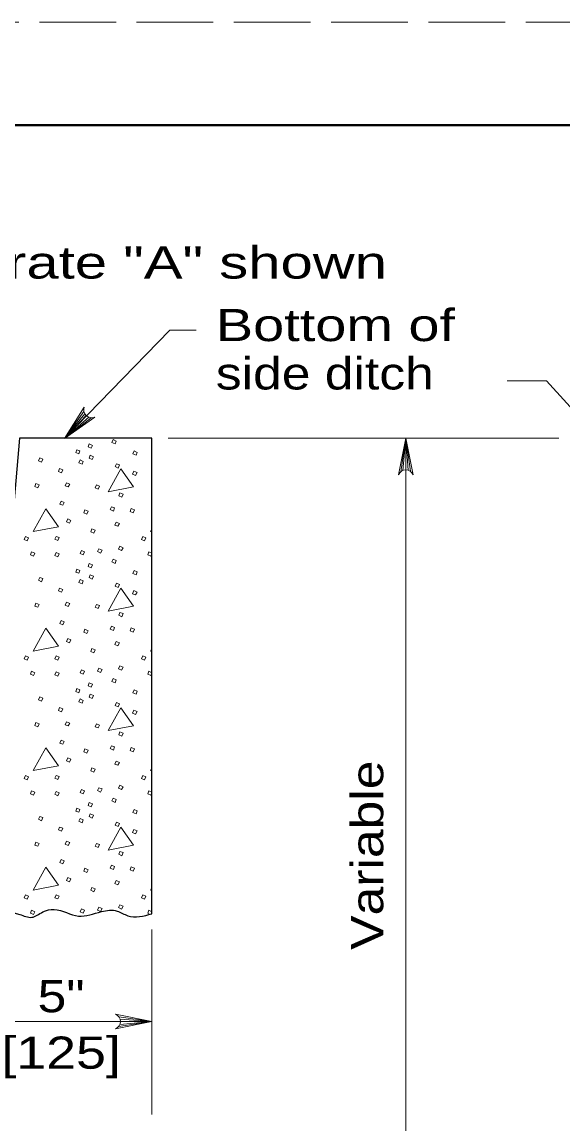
# Model space of a CAD drawing. Extents: x 1036.7 to 1070.7, y 883.9 to 905.9.
# Drawn here: x 1055.59 to 1058.21, y 900.56 to 905.91 of the extents above; entities that cross this region are included whole.
import ezdxf
from ezdxf.enums import TextEntityAlignment as Align

# ---------------------------------------------------------------- set-up
doc = ezdxf.new("R2010")
doc.units = 0
doc.header["$LTSCALE"] = 0.062
doc.linetypes.add('LONG_DASHED', pattern=[7.5, 6, -1.5])
doc.layers.add('1', color=7, linetype='Continuous', lineweight=13)

msp = doc.modelspace()

# ---------------------------------------------------------------- linework, layer by layer
at = {"layer": '1', "lineweight": 25}
for p, q in [((1038.67333, 905.40825), (1070.17333, 905.40825)), ((1056.21542, 901.58258), (1056.21542, 903.88892))]:
    msp.add_line(p, q, dxfattribs=at)
at = {"layer": '1'}
for p, q in [((1055.79083, 903.88783), (1056.30283, 904.41408)), ((1056.4305, 904.41408), (1056.30283, 904.41408)), ((1057.94, 904.16733), (1058.131, 904.16733)), ((1058.37525, 903.8975), (1058.131, 904.16733)), ((1055.88492, 904.0195), (1055.79083, 903.88783)), ((1055.88917, 904.00792), (1055.79083, 903.88783)), ((1055.89625, 903.99892), (1055.79083, 903.88783)), ((1055.90867, 903.99108), (1055.79083, 903.88783)), ((1055.92042, 903.98842), (1055.79083, 903.88783)), ((1056.29358, 903.88892), (1058.18042, 903.88892)), ((1058.19033, 903.88892), (1056.29992, 903.88892)), ((1057.42275, 903.72675), (1057.4475, 903.88892)), ((1057.43308, 903.73292), (1057.4475, 903.88892)), ((1057.4475, 900.62258), (1057.4475, 903.88892)), ((1057.4475, 903.73575), (1057.4475, 903.88892)), ((1057.45883, 903.73408), (1057.4475, 903.88892)), ((1057.46992, 903.72867), (1057.4475, 903.88892)), ((1056.20117, 903.338), (1056.21542, 903.33133)), ((1056.20117, 902.75833), (1056.21542, 902.75167)), ((1056.20117, 902.17867), (1056.21542, 902.172)), ((1056.20117, 901.599), (1056.21542, 901.59233)), ((1056.21542, 901.59025), (1056.212, 901.58233)), ((1056.21542, 901.50508), (1056.21542, 900.60858)), ((1055.32617, 901.05958), (1056.21542, 901.05958)), ((1056.05333, 901.03475), (1056.21542, 901.05958)), ((1056.05517, 901.082), (1056.21542, 901.05958)), ((1056.05942, 901.04517), (1056.21542, 901.05958)), ((1056.06058, 901.07092), (1056.21542, 901.05958)), ((1056.06225, 901.05958), (1056.21542, 901.05958)), ((1057.4475, 900.62258), (1057.4475, 899.32858))]:
    msp.add_line(p, q, dxfattribs=at)
at = {"layer": '1', "linetype": 'LONG_DASHED'}
msp.add_lwpolyline([(1036.67333, 883.90825), (1070.67333, 883.90825), (1070.67333, 905.90825), (1036.67333, 905.90825)], close=True, dxfattribs=at)
at = {"layer": '1', "lineweight": 40}
msp.add_lwpolyline([(1038.67333, 905.40825), (1070.17333, 905.40825), (1070.17333, 884.40825), (1038.67333, 884.40825)], close=True, dxfattribs=at)
msp.add_lwpolyline([(1038.67333, 905.40825), (1070.17333, 905.40825), (1070.17333, 884.40825), (1038.67333, 884.40825)], close=True, dxfattribs=at)
at = {"layer": '1'}
for points in [[(1055.93833, 903.99183), (1055.79083, 903.88783), (1055.887, 904.04058)], [(1057.41208, 903.71192), (1057.4475, 903.88892), (1057.48292, 903.71192)], [(1056.21542, 903.44892), (1056.20817, 903.43592), (1056.21542, 903.43733)], [(1056.21542, 903.32925), (1056.21017, 903.317), (1056.19517, 903.324), (1056.20117, 903.338)], [(1056.21542, 902.86925), (1056.20817, 902.85625), (1056.21542, 902.85767)], [(1056.21542, 902.74958), (1056.21017, 902.73733), (1056.19517, 902.74433), (1056.20117, 902.75833)], [(1056.21542, 902.28958), (1056.20817, 902.27658), (1056.21542, 902.278)], [(1056.21542, 902.16992), (1056.21017, 902.15767), (1056.19517, 902.16467), (1056.20117, 902.17867)], [(1056.21542, 901.70992), (1056.20817, 901.69692), (1056.21542, 901.69833)], [(1056.20267, 901.5815), (1056.19517, 901.585), (1056.20117, 901.599)], [(1056.03842, 901.02417), (1056.21542, 901.05958), (1056.03842, 901.095)]]:
    msp.add_lwpolyline(points, dxfattribs=at)
at = {"layer": '1', "lineweight": 25}
msp.add_lwpolyline([(1056.21542, 903.88892), (1055.57342, 903.88892), (1055.53433, 903.43767)], dxfattribs=at)
at = {"layer": '1'}
for points in [[(1056.02725, 903.88267), (1056.04225, 903.87567), (1056.03625, 903.86167), (1056.02125, 903.86867)], [(1055.85133, 903.83367), (1055.86633, 903.82767), (1055.86033, 903.81367), (1055.84533, 903.81967)], [(1055.91133, 903.86167), (1055.92633, 903.85467), (1055.92033, 903.84067), (1055.90533, 903.84667)], [(1056.12925, 903.82767), (1056.14417, 903.82067), (1056.13825, 903.80667), (1056.12325, 903.81267)], [(1055.67142, 903.79367), (1055.68642, 903.78767), (1055.67942, 903.77267), (1055.66442, 903.77967)], [(1055.86733, 903.78367), (1055.88233, 903.77667), (1055.87633, 903.76275), (1055.86133, 903.76975)], [(1055.91633, 903.80667), (1055.93133, 903.79967), (1055.92533, 903.78567), (1055.91033, 903.79267)], [(1056.04325, 903.76575), (1056.05825, 903.75975), (1056.05225, 903.74475), (1056.03725, 903.75175)], [(1055.76742, 903.74175), (1055.78242, 903.73575), (1055.77642, 903.72175), (1055.76142, 903.72775)], [(1056.06425, 903.74075), (1056.00225, 903.62975), (1056.12525, 903.65375)], [(1056.12825, 903.72975), (1056.14317, 903.72275), (1056.13625, 903.70875), (1056.12125, 903.71475)], [(1055.65242, 903.66875), (1055.66742, 903.66275), (1055.66142, 903.64875), (1055.64642, 903.65475)], [(1055.80133, 903.67275), (1055.81633, 903.66675), (1055.80933, 903.65275), (1055.79433, 903.65875)], [(1055.94633, 903.66275), (1055.96133, 903.65675), (1055.95433, 903.64275), (1055.93933, 903.64875)], [(1056.06025, 903.62383), (1056.07525, 903.61783), (1056.06925, 903.60283), (1056.05425, 903.60983)], [(1055.70042, 903.54683), (1055.63842, 903.43592), (1055.76142, 903.45992)], [(1055.77442, 903.58383), (1055.78933, 903.57783), (1055.78342, 903.56383), (1055.76842, 903.56983)], [(1056.01925, 903.55683), (1056.03425, 903.55083), (1056.02825, 903.53583), (1056.01325, 903.54283)], [(1056.11525, 903.54883), (1056.13025, 903.54183), (1056.12425, 903.52783), (1056.10925, 903.53383)], [(1055.80733, 903.49783), (1055.82233, 903.49083), (1055.81533, 903.47692), (1055.80033, 903.48292)], [(1055.89033, 903.54183), (1055.90533, 903.53483), (1055.89933, 903.52083), (1055.88433, 903.52783)], [(1055.92433, 903.44892), (1055.93933, 903.44292), (1055.93333, 903.42792), (1055.91833, 903.43492)], [(1056.04225, 903.48192), (1056.05725, 903.47592), (1056.05025, 903.46192), (1056.03525, 903.46792)], [(1055.6015, 903.41292), (1055.61642, 903.40592), (1055.61042, 903.39192), (1055.5955, 903.39792)], [(1055.75042, 903.41292), (1055.76542, 903.40692), (1055.75842, 903.39292), (1055.74342, 903.39892)], [(1056.17117, 903.41292), (1056.18617, 903.40592), (1056.18017, 903.39192), (1056.16517, 903.39792)], [(1055.63142, 903.338), (1055.64642, 903.331), (1055.64042, 903.317), (1055.62542, 903.324)], [(1055.75042, 903.335), (1055.76542, 903.329), (1055.75842, 903.314), (1055.74342, 903.321)], [(1055.87333, 903.34492), (1055.88833, 903.338), (1055.88233, 903.324), (1055.86733, 903.33)], [(1055.95833, 903.35292), (1055.97325, 903.34692), (1055.96625, 903.332), (1055.95133, 903.339)], [(1056.06025, 903.36492), (1056.07525, 903.35792), (1056.06825, 903.34392), (1056.05325, 903.35092)], [(1055.91133, 903.282), (1055.92633, 903.275), (1055.92033, 903.261), (1055.90533, 903.267)], [(1056.02725, 903.303), (1056.04225, 903.296), (1056.03625, 903.282), (1056.02125, 903.289)], [(1055.85133, 903.254), (1055.86633, 903.248), (1055.86033, 903.234), (1055.84533, 903.24)], [(1055.91633, 903.227), (1055.93133, 903.22), (1055.92533, 903.206), (1055.91033, 903.213)], [(1056.12925, 903.248), (1056.14417, 903.241), (1056.13825, 903.227), (1056.12325, 903.233)], [(1055.67142, 903.214), (1055.68642, 903.208), (1055.67942, 903.193), (1055.66442, 903.2)], [(1055.86733, 903.204), (1055.88233, 903.197), (1055.87633, 903.18308), (1055.86133, 903.19008)], [(1056.04325, 903.18608), (1056.05825, 903.18008), (1056.05225, 903.16508), (1056.03725, 903.17208)], [(1055.76742, 903.16208), (1055.78242, 903.15608), (1055.77642, 903.14208), (1055.76142, 903.14808)], [(1056.06425, 903.16108), (1056.00225, 903.05008), (1056.12525, 903.07408)], [(1056.12825, 903.15008), (1056.14317, 903.14308), (1056.13625, 903.12908), (1056.12125, 903.13508)], [(1055.65242, 903.08908), (1055.66742, 903.08308), (1055.66142, 903.06908), (1055.64642, 903.07508)], [(1055.80133, 903.09308), (1055.81633, 903.08708), (1055.80933, 903.07308), (1055.79433, 903.07908)], [(1055.94633, 903.08308), (1055.96133, 903.07708), (1055.95433, 903.06308), (1055.93933, 903.06908)], [(1056.06025, 903.04417), (1056.07525, 903.03817), (1056.06925, 903.02317), (1056.05425, 903.03017)], [(1055.70042, 902.96717), (1055.63842, 902.85625), (1055.76142, 902.88025)], [(1055.77442, 903.00417), (1055.78933, 902.99817), (1055.78342, 902.98417), (1055.76842, 902.99017)], [(1055.89033, 902.96217), (1055.90533, 902.95517), (1055.89933, 902.94117), (1055.88433, 902.94817)], [(1056.01925, 902.97717), (1056.03425, 902.97117), (1056.02825, 902.95617), (1056.01325, 902.96317)], [(1056.11525, 902.96917), (1056.13025, 902.96217), (1056.12425, 902.94817), (1056.10925, 902.95417)], [(1055.80733, 902.91817), (1055.82233, 902.91117), (1055.81533, 902.89725), (1055.80033, 902.90325)], [(1056.04225, 902.90225), (1056.05725, 902.89625), (1056.05025, 902.88225), (1056.03525, 902.88825)], [(1055.92433, 902.86925), (1055.93933, 902.86325), (1055.93333, 902.84825), (1055.91833, 902.85525)], [(1055.6015, 902.83325), (1055.61642, 902.82625), (1055.61042, 902.81225), (1055.5955, 902.81825)], [(1055.75042, 902.83325), (1055.76542, 902.82725), (1055.75842, 902.81325), (1055.74342, 902.81925)], [(1056.17117, 902.83325), (1056.18617, 902.82625), (1056.18017, 902.81225), (1056.16517, 902.81825)], [(1055.63142, 902.75833), (1055.64642, 902.75133), (1055.64042, 902.73733), (1055.62542, 902.74433)], [(1055.75042, 902.75533), (1055.76542, 902.74933), (1055.75842, 902.73433), (1055.74342, 902.74133)], [(1055.87333, 902.76525), (1055.88833, 902.75833), (1055.88233, 902.74433), (1055.86733, 902.75033)], [(1055.95833, 902.77325), (1055.97325, 902.76725), (1055.96625, 902.75233), (1055.95133, 902.75933)], [(1056.06025, 902.78525), (1056.07525, 902.77825), (1056.06825, 902.76425), (1056.05325, 902.77125)], [(1055.91133, 902.70233), (1055.92633, 902.69533), (1055.92033, 902.68133), (1055.90533, 902.68733)], [(1056.02725, 902.72333), (1056.04225, 902.71633), (1056.03625, 902.70233), (1056.02125, 902.70933)], [(1055.67142, 902.63433), (1055.68642, 902.62833), (1055.67942, 902.61342), (1055.66442, 902.62033)], [(1055.85133, 902.67433), (1055.86633, 902.66833), (1055.86033, 902.65433), (1055.84533, 902.66033)], [(1055.91633, 902.64733), (1055.93133, 902.64033), (1055.92533, 902.62633), (1055.91033, 902.63333)], [(1056.12925, 902.66833), (1056.14417, 902.66133), (1056.13825, 902.64733), (1056.12325, 902.65333)], [(1055.76742, 902.58242), (1055.78242, 902.57642), (1055.77642, 902.56242), (1055.76142, 902.56842)], [(1055.86733, 902.62433), (1055.88233, 902.61733), (1055.87633, 902.60342), (1055.86133, 902.61042)], [(1056.06425, 902.58142), (1056.00225, 902.4705), (1056.12525, 902.49442)], [(1056.04325, 902.60642), (1056.05825, 902.60042), (1056.05225, 902.58542), (1056.03725, 902.59242)], [(1056.12825, 902.57042), (1056.14317, 902.56342), (1056.13625, 902.54942), (1056.12125, 902.55542)], [(1055.65242, 902.50942), (1055.66742, 902.50342), (1055.66142, 902.48942), (1055.64642, 902.49542)], [(1055.80133, 902.51342), (1055.81633, 902.50742), (1055.80933, 902.49342), (1055.79433, 902.49942)], [(1055.94633, 902.50342), (1055.96133, 902.49742), (1055.95433, 902.48342), (1055.93933, 902.48942)], [(1055.77442, 902.4245), (1055.78933, 902.4185), (1055.78342, 902.4045), (1055.76842, 902.4105)], [(1056.06025, 902.4645), (1056.07525, 902.4585), (1056.06925, 902.4435), (1056.05425, 902.4505)], [(1055.70042, 902.3875), (1055.63842, 902.27658), (1055.76142, 902.30058)], [(1055.89033, 902.3825), (1055.90533, 902.3755), (1055.89933, 902.3615), (1055.88433, 902.3685)], [(1056.01925, 902.3975), (1056.03425, 902.3915), (1056.02825, 902.3765), (1056.01325, 902.3835)], [(1056.11525, 902.3895), (1056.13025, 902.3825), (1056.12425, 902.3685), (1056.10925, 902.3745)], [(1055.80733, 902.3385), (1055.82233, 902.3315), (1055.81533, 902.31758), (1055.80033, 902.32358)], [(1056.04225, 902.32258), (1056.05725, 902.31658), (1056.05025, 902.30258), (1056.03525, 902.30858)], [(1055.92433, 902.28958), (1055.93933, 902.28358), (1055.93333, 902.26858), (1055.91833, 902.27558)], [(1055.6015, 902.25358), (1055.61642, 902.24658), (1055.61042, 902.23258), (1055.5955, 902.23858)], [(1055.75042, 902.25358), (1055.76542, 902.24758), (1055.75842, 902.23358), (1055.74342, 902.23958)], [(1056.17117, 902.25358), (1056.18617, 902.24658), (1056.18017, 902.23258), (1056.16517, 902.23858)], [(1055.63142, 902.17867), (1055.64642, 902.17167), (1055.64042, 902.15767), (1055.62542, 902.16467)], [(1055.75042, 902.17567), (1055.76542, 902.16967), (1055.75842, 902.15467), (1055.74342, 902.16167)], [(1055.87333, 902.18558), (1055.88833, 902.17867), (1055.88233, 902.16467), (1055.86733, 902.17067)], [(1055.95833, 902.19358), (1055.97325, 902.18758), (1055.96625, 902.17267), (1055.95133, 902.17967)], [(1056.06025, 902.20558), (1056.07525, 902.19858), (1056.06825, 902.18458), (1056.05325, 902.19158)], [(1055.91133, 902.12267), (1055.92633, 902.11567), (1055.92033, 902.10167), (1055.90533, 902.10767)], [(1056.02725, 902.14367), (1056.04225, 902.13667), (1056.03625, 902.12267), (1056.02125, 902.12967)], [(1055.67142, 902.05467), (1055.68642, 902.04867), (1055.67942, 902.03375), (1055.66442, 902.04067)], [(1055.85133, 902.09467), (1055.86633, 902.08867), (1055.86033, 902.07467), (1055.84533, 902.08067)], [(1055.91633, 902.06767), (1055.93133, 902.06067), (1055.92533, 902.04667), (1055.91033, 902.05367)], [(1056.12925, 902.08867), (1056.14417, 902.08167), (1056.13825, 902.06767), (1056.12325, 902.07367)], [(1055.76742, 902.00275), (1055.78242, 901.99675), (1055.77642, 901.98275), (1055.76142, 901.98875)], [(1055.86733, 902.04467), (1055.88233, 902.03767), (1055.87633, 902.02375), (1055.86133, 902.03075)], [(1056.06425, 902.00175), (1056.00225, 901.89083), (1056.12525, 901.91475)], [(1056.04325, 902.02675), (1056.05825, 902.02075), (1056.05225, 902.00575), (1056.03725, 902.01275)], [(1056.12825, 901.99075), (1056.14317, 901.98375), (1056.13625, 901.96975), (1056.12125, 901.97575)], [(1055.65242, 901.92975), (1055.66742, 901.92375), (1055.66142, 901.90975), (1055.64642, 901.91575)], [(1055.80133, 901.93375), (1055.81633, 901.92775), (1055.80933, 901.91375), (1055.79433, 901.91975)], [(1055.94633, 901.92375), (1055.96133, 901.91775), (1055.95433, 901.90375), (1055.93933, 901.90975)], [(1055.77442, 901.84483), (1055.78933, 901.83883), (1055.78342, 901.82483), (1055.76842, 901.83083)], [(1056.06025, 901.88483), (1056.07525, 901.87883), (1056.06925, 901.86383), (1056.05425, 901.87083)], [(1055.70042, 901.80783), (1055.63842, 901.69692), (1055.76142, 901.72092)], [(1055.89033, 901.80283), (1055.90533, 901.79583), (1055.89933, 901.78183), (1055.88433, 901.78883)], [(1056.01925, 901.81783), (1056.03425, 901.81183), (1056.02825, 901.79683), (1056.01325, 901.80383)], [(1056.11525, 901.80983), (1056.13025, 901.80283), (1056.12425, 901.78883), (1056.10925, 901.79483)], [(1055.80733, 901.75883), (1055.82233, 901.75183), (1055.81533, 901.73792), (1055.80033, 901.74392)], [(1056.04225, 901.74292), (1056.05725, 901.73692), (1056.05025, 901.72292), (1056.03525, 901.72892)], [(1055.6015, 901.67392), (1055.61642, 901.66692), (1055.61042, 901.65292), (1055.5955, 901.65892)], [(1055.75042, 901.67392), (1055.76542, 901.66792), (1055.75842, 901.65392), (1055.74342, 901.65992)], [(1055.92433, 901.70992), (1055.93933, 901.70392), (1055.93333, 901.68892), (1055.91833, 901.69592)], [(1056.17117, 901.67392), (1056.18617, 901.66692), (1056.18017, 901.65292), (1056.16517, 901.65892)], [(1056.06025, 901.62592), (1056.07525, 901.61892), (1056.06825, 901.60492), (1056.05325, 901.61192)], [(1055.63142, 901.599), (1055.64642, 901.592), (1055.64042, 901.578), (1055.62542, 901.585)], [(1055.87333, 901.60592), (1055.88833, 901.599), (1055.88233, 901.585), (1055.86733, 901.591)], [(1055.95833, 901.61392), (1055.97325, 901.60792), (1055.96625, 901.593), (1055.95133, 901.6)]]:
    msp.add_lwpolyline(points, close=True, dxfattribs=at)
for centre, start, end in [((1055.9225, 904.02663), 158.59296, 294.41909), ((1057.44755, 903.6976), 22.08782, 157.91395), ((1056.02413, 901.0596), 292.08605, 67.91218)]:
    msp.add_arc(centre, 0.0382, start, end, dxfattribs=at)
at = {"layer": '1', "lineweight": 25}
msp.add_spline([(1055.32258, 901.59142), (1055.44183, 901.593), (1055.57383, 901.57925), (1055.63208, 901.56492), (1055.68575, 901.59117), (1055.74133, 901.60308), (1055.85883, 901.57108), (1055.96992, 901.59283), (1056.047, 901.59558), (1056.0985, 901.57258), (1056.21542, 901.58258)], degree=3, dxfattribs=at)

# ---------------------------------------------------------------- texts
at = {"layer": '1'}
for s, width, p in [('Grate "A" shown', 1.35, (1055.2935, 904.66375)), ('Bottom of', 1.3, (1056.52575, 904.36033)), ('side ditch', 1.2, (1056.52575, 904.12567))]:
    msp.add_text(s, height=0.156, dxfattribs=dict(at, width=width)).set_placement(p)
at = {"layer": '1', "width": 1.2}
msp.add_text('Variable', height=0.156, rotation=90, dxfattribs=at).set_placement((1057.338, 901.40717))
at = {"layer": '1'}
for s, width, p in [('5"', 1.2, (1055.77471, 901.1045)), ('[125]', 1.25, (1055.77467, 900.8305))]:
    msp.add_text(s, height=0.156, dxfattribs=dict(at, width=width)).set_placement(p, align=Align.CENTER)

doc.saveas('drawing.dxf')
